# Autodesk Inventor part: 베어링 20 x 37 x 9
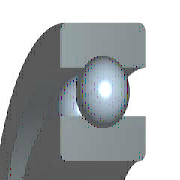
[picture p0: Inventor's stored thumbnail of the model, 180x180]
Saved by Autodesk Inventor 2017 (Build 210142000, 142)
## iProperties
IsCustomPart: 1
Created: 2012-02
Part Number: 베어링 20 x 37 x 9
Material: 강철, 연강
Description: 깊은 그루브 볼 베어링
Document SubType Name: Modeling
Standard: KS B 2023
Designer: mduedu
Standards Organization: KS
Language: ko-KR
Size Designation: 6904 - 20 x 37 x 9
Categories: <MemberInstance><Categories><Category DisplayName="샤프트 부품" InternalName="7f7aeb1f-a693-4053-b835-cee3144e0d98" Mnemonic="SHFT"><Category DisplayName="베어링" Inter
Density: 7.86 g/cm^3
Mass: 36.2614 g
Surface Area: 48.5817 cm^2
Volume: 4.61341 cm^3
Appearance: 노란색
Author: mduedu
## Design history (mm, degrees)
sketch "스케치" dims "d0" = 4.42 (= -0.26 x WD + 0.26 x BD)
  geometry: L1 (2.29, 14.25)-(6.71, 14.25); L2 (4.5, 14.25)-(4.5, 12.04); L3 (4.5, 14.25)-(4.5, 16.46); L4 (2.858, 12.771)-(0, 12.771); L5 (0, 10)-(9, 10); L6 (2.858, 15.729)-(0, 15.729); L7 (0, 18.5)-(9, 18.5); L8 (9, 10)-(9, 12.771); L9 (6.142, 12.771)-(9, 12.771); L10 (6.142, 15.729)-(9, 15.729); L11 (9, 18.5)-(9, 15.729); L12 (-1.4, 0)-(8.4, 0) reference; L13 (0, -0.3)-(0, 5.3) reference
  constraints: 22 end point, 4 point on line, 2 collinear, 2 perpendicular, 2 symmetric about line, 1 midpoint, 1 parallel, 14 other
  dimensions: "d9" = 20 diameter of L5 L12 (= WD); "d11" = 37 diameter of L7 L12 (= BD); "d12" = 9 distance between parallel lines of L8 L13 (= KB); "d13" = 25.542 diameter of L9 L12 (= 0.326 x BD + 0.674 x WD)
revolve "본체" stored, may be unused: angle "d6" = 90 deg
revolve "볼" stored, may be unused: angle "d7" = 90 deg
pattern_circular "IDS_ARRAYBALL[SIMPL:T]" dims angle "d3" = 360 deg
body "Solid1"
fillet "모깎기1" dims "d1" = 0.3 (= KRS)
other parameters: "WD" = 20 [user parameter; used in 5 equation terms], "BD" = 37 [user parameter; used in 5 equation terms], "KB" = 9 [user parameter; used in 1 equation term], "KRS" = 0.3 [user parameter; used in 1 equation term], "d4" = 0, "d5" = 0, "d8" = 0, "d14" = 0, "d15" = 0, "BBA" = 0 [user parameter], "BC0" = 3304000 [user parameter], "BC" = 6184000 [user parameter], "BR" = 18.5 (= 0.5 x BD) [user parameter]
